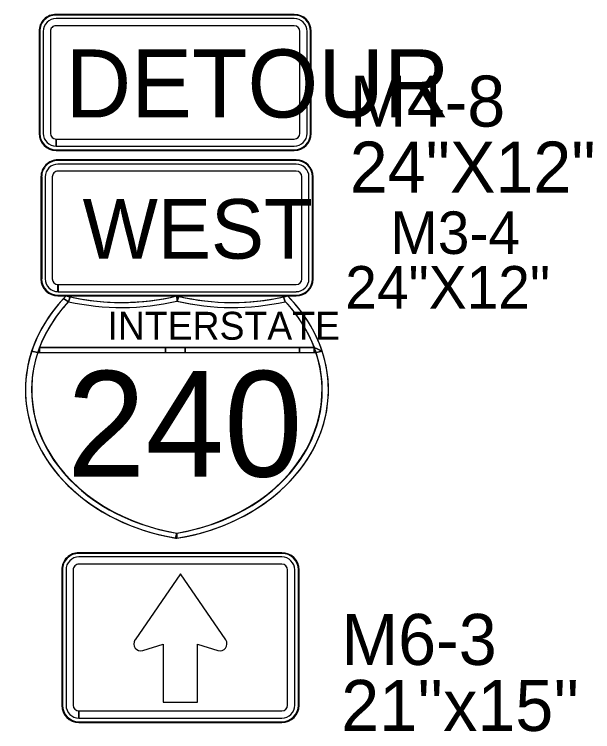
# Model space of a CAD drawing. Extents: x 886234 to 968767, y 455416 to 684046.
# Drawn here: x 909188 to 910208, y 514345 to 515610 of the extents above; entities that cross this region are included whole.
import ezdxf

# ---------------------------------------------------------------- set-up
doc = ezdxf.new("R2010")
doc.units = 0
for name, color, linetype in [('TC DEV SIGN BLACK 239', 7, 'Continuous'), ('TC DEV SIGN BLACK ZERO', 7, 'Continuous'), ('TC DEV SIGN ORANGE', 7, 'Continuous'), ('TC DEV SIGN WHITE', 7, 'Continuous'), ('TC LABEL TEXT', 7, 'Continuous')]:
    doc.layers.add(name, color=color, linetype=linetype)

msp = doc.modelspace()

# ---------------------------------------------------------------- linework, layer by layer
at = {"layer": 'TC DEV SIGN BLACK 239'}
for p, q in [((909684.9, 515346), (909264.8, 515346)), ((909684.9, 515333.5), (909264.8, 515333.5)), ((909242.3, 515323.5), (909242.3, 515143.5)), ((909254.8, 515323.5), (909254.8, 515143.5)), ((909694.9, 515143.5), (909694.9, 515323.5)), ((909707.4, 515143.5), (909707.4, 515323.5)), ((909264.8, 515121), (909264.8, 515133.5)), ((909265, 515133.5), (909684.9, 515133.5)), ((909265, 515133.5), (909265, 515121)), ((909265, 515121), (909684.9, 515121)), ((909659.6, 514653.1), (909301.8, 514653.1)), ((909279, 514630.3), (909279, 514391.7)), ((909291.7, 514630.3), (909291.6, 514391.7)), ((909659.6, 514640.4), (909301.8, 514640.4)), ((909669.7, 514391.7), (909669.7, 514630.3)), ((909682.4, 514391.7), (909682.4, 514630.3)), ((909301.8, 514368.9), (909301.8, 514381.6)), ((909301.9, 514381.6), (909659.6, 514381.6)), ((909301.9, 514381.6), (909301.9, 514368.9)), ((909301.9, 514368.9), (909659.6, 514368.9))]:
    msp.add_line(p, q, dxfattribs=at)
for points in [[(909560.8, 514506.8), (909480.7, 514623.4), (909400.7, 514506.8)], [(909560.8, 514506.8), (909480.7, 514623.4), (909400.7, 514506.8)], [(909560.8, 514506.8), (909480.7, 514623.4), (909400.7, 514506.8)], [(909414.4, 514488.3), (909450.2, 514499.6), (909450.2, 514397.3), (909511.1, 514397.3)], [(909414.4, 514488.3), (909450.2, 514499.6), (909450.2, 514397.3), (909511.1, 514397.3)], [(909414.4, 514488.3), (909450.2, 514499.6), (909450.2, 514397.3), (909511.1, 514397.3)], [(909511.1, 514397.3), (909511.1, 514499.6), (909547, 514488.3)], [(909511.1, 514397.3), (909511.1, 514499.6), (909547, 514488.3)], [(909511.1, 514397.3), (909511.1, 514499.6), (909547, 514488.3)]]:
    msp.add_lwpolyline(points, dxfattribs=at)
for centre, start, end in [((909410.7, 514499.8), 145.5508, 287.601), ((909410.7, 514499.8), 145.5508, 287.601), ((909410.7, 514499.8), 145.5508, 287.601), ((909550.7, 514499.8), 252.399, 34.4492), ((909550.7, 514499.8), 252.399, 34.4492), ((909550.7, 514499.8), 252.399, 34.4492)]:
    msp.add_arc(centre, 12.2, start, end, dxfattribs=at)
for centre, major_axis, start_param, end_param in [((909264.8, 515323.5), (22.5, 0), 1.570796, 3.141593), ((909684.9, 515323.5), (22.5, 0), 0, 1.570796), ((909264.8, 515323.5), (10, 0), 1.570796, 3.141593), ((909684.9, 515323.5), (10, 0), 0, 1.570796), ((909264.8, 515143.5), (22.5, 0), 3.141593, 4.712389), ((909264.8, 515143.5), (10, 0), 3.141593, 4.712389), ((909684.9, 515143.5), (22.5, 0), 4.712389, 6.283185), ((909684.9, 515143.5), (10, 0), 4.712389, 6.283185), ((909301.8, 514630.3), (22.8, 0), 1.570796, 3.141593), ((909659.6, 514630.3), (22.8, 0), 0, 1.570796), ((909301.8, 514630.3), (10.1, 0), 1.570796, 3.141593), ((909659.6, 514630.3), (10.1, 0), 0, 1.570796), ((909301.8, 514391.7), (22.8, 0), 3.141593, 4.712389), ((909301.8, 514391.7), (10.1, 0), 3.141593, 4.712389), ((909659.6, 514391.7), (22.8, 0), 4.712389, 6.283185), ((909659.6, 514391.7), (10.1, 0), 4.712389, 6.283185)]:
    msp.add_ellipse(centre, major_axis=major_axis, ratio=0.999865, start_param=start_param, end_param=end_param, dxfattribs=at)
at = {"layer": 'TC DEV SIGN BLACK ZERO'}
for p, q in [((909681.5, 515610.1), (909261.4, 515610.1)), ((909261.4, 515608.8), (909261.4, 515608.8)), ((909681.5, 515608.8), (909261.4, 515608.8)), ((909681.5, 515608.8), (909681.5, 515608.8)), ((909681.5, 515602.6), (909261.4, 515602.6)), ((909231.4, 515580.1), (909231.4, 515400.1)), ((909232.7, 515580.1), (909232.7, 515400.1)), ((909232.7, 515580.1), (909232.7, 515580.1)), ((909238.9, 515580.1), (909238.9, 515400.1)), ((909251.4, 515580.1), (909251.4, 515400.1)), ((909681.5, 515590.1), (909261.4, 515590.1)), ((909691.5, 515400.1), (909691.5, 515580.1)), ((909704, 515400.1), (909704, 515580.1)), ((909710.2, 515580.1), (909710.2, 515580.1)), ((909710.2, 515400.1), (909710.2, 515580.1)), ((909711.5, 515400.1), (909711.5, 515580.1)), ((909232.7, 515400.1), (909232.7, 515400.1)), ((909261.4, 515377.6), (909261.4, 515390.1)), ((909261.5, 515390.1), (909681.5, 515390.1)), ((909261.5, 515390.1), (909261.5, 515377.6)), ((909710.2, 515400.1), (909710.2, 515400.1)), ((909261.5, 515377.6), (909681.5, 515377.6)), ((909261.4, 515370.1), (909261.4, 515371.3)), ((909261.4, 515371.3), (909261.4, 515371.3)), ((909261.4, 515371.3), (909681.5, 515371.3)), ((909261.4, 515371.3), (909261.4, 515370.1)), ((909261.4, 515370.1), (909681.5, 515370.1)), ((909681.5, 515371.3), (909681.5, 515371.3)), ((909684.9, 515353.5), (909264.8, 515353.5)), ((909264.8, 515352.3), (909264.8, 515352.3)), ((909684.9, 515352.3), (909264.8, 515352.3)), ((909684.9, 515352.3), (909684.9, 515352.3)), ((909234.8, 515323.5), (909234.8, 515143.5)), ((909236.1, 515323.5), (909236.1, 515143.5)), ((909236.1, 515323.5), (909236.1, 515323.5)), ((909713.6, 515323.5), (909713.7, 515323.5)), ((909713.7, 515143.5), (909713.7, 515323.5)), ((909714.9, 515143.5), (909714.9, 515323.5)), ((909236.1, 515143.5), (909236.1, 515143.5)), ((909713.7, 515143.5), (909713.6, 515143.5)), ((909264.8, 515113.5), (909264.8, 515114.8)), ((909264.8, 515114.8), (909264.8, 515114.8)), ((909264.9, 515114.8), (909684.9, 515114.8)), ((909264.9, 515114.8), (909264.9, 515113.5)), ((909264.9, 515113.5), (909684.9, 515113.5)), ((909283.6, 515103.3), (909286.6, 515111.9)), ((909474.9, 515104.3), (909474.6, 515113.6)), ((909474.9, 515105), (909474.6, 515113.6)), ((909662.6, 515111.9), (909665.6, 515103.3)), ((909684.9, 515114.8), (909684.9, 515114.8)), ((909232.3, 515022.4), (909716.9, 515022.4)), ((909454.2, 515022.4), (909232.3, 515022.4)), ((909489.4, 515022.4), (909454.2, 515022.4)), ((909690.7, 515022.4), (909489.4, 515022.4)), ((909716.9, 515022.4), (909690.7, 515022.4)), ((909730.8, 515015.8), (909716.9, 515022.4)), ((909229.1, 515013.5), (909720.1, 515013.5)), ((909229.1, 515013.5), (909232.3, 515013.5)), ((909232.3, 515013.5), (909454.2, 515013.5)), ((909454.2, 515013.5), (909489.4, 515013.5)), ((909489.4, 515013.5), (909690.7, 515013.5)), ((909690.7, 515013.5), (909716.9, 515013.5)), ((909719.8, 515014.2), (909716.9, 515013.5)), ((909716.9, 515013.5), (909720.1, 515013.5)), ((909207.4, 514949.2), (909207.4, 514946.6)), ((909741.8, 514946.5), (909741.8, 514949.3)), ((909474.6, 514686.1), (909474.6, 514695.2)), ((909659.6, 514660.7), (909301.8, 514660.7)), ((909301.8, 514659.4), (909301.8, 514659.5)), ((909659.6, 514659.4), (909301.8, 514659.5)), ((909659.6, 514659.4), (909659.6, 514659.4)), ((909271.4, 514630.3), (909271.4, 514391.7)), ((909272.6, 514630.3), (909272.6, 514391.7)), ((909272.6, 514630.3), (909272.6, 514630.3)), ((909688.7, 514630.3), (909688.7, 514630.3)), ((909688.7, 514391.7), (909688.7, 514630.3)), ((909690, 514391.7), (909690, 514630.3)), ((909272.6, 514391.7), (909272.6, 514391.7)), ((909688.7, 514391.7), (909688.7, 514391.7)), ((909301.8, 514361.3), (909301.8, 514362.6)), ((909301.8, 514362.6), (909301.8, 514362.6)), ((909301.8, 514362.6), (909659.6, 514362.6)), ((909301.8, 514362.6), (909301.8, 514361.3)), ((909301.8, 514361.3), (909659.6, 514361.3)), ((909659.6, 514362.6), (909659.6, 514362.6))]:
    msp.add_line(p, q, dxfattribs=at)
for points in [[(909279.4, 515113.6), (909279.4, 515113.6), (909279.4, 515113.6)], [(909286.6, 515111.9), (909283.6, 515103.3)], [(909474.9, 515113.5), (909474.9, 515105), (909478, 515112.8)], [(909478, 515112.8), (909474.9, 515104.3)], [(909665.6, 515103.3), (909662.6, 515111.9)], [(909669.8, 515113.6), (909669.8, 515113.6), (909669.8, 515113.6)], [(909274.7, 515108.7), (909283.6, 515103.3)], [(909283.6, 515103.3), (909274.7, 515108.7)], [(909474.6, 515104.3), (909474.9, 515105)], [(909232.3, 515022.4), (909232.3, 515013.5)], [(909232.3, 515013.5), (909232.3, 515022.4)], [(909454.2, 515013.5), (909454.2, 515022.4)], [(909454.2, 515022.4), (909454.2, 515013.5)], [(909489.4, 515022.4), (909489.4, 515013.5)], [(909489.4, 515013.5), (909489.4, 515022.4)], [(909690.7, 515013.5), (909690.7, 515022.4)], [(909690.7, 515022.4), (909690.7, 515013.5)], [(909716.9, 515022.4), (909730.8, 515015.8)], [(909716.9, 515013.5), (909716.9, 515022.4)], [(909716.9, 515022.4), (909716.9, 515013.5), (909719.8, 515014.2), (909716.9, 515022.4)], [(909218.4, 515015.8), (909229.1, 515013.5)], [(909229.1, 515013.5), (909218.4, 515015.8)], [(909720.1, 515013.5), (909719.8, 515014.2)], [(909730.8, 515015.8), (909720.1, 515013.5)], [(909720.1, 515013.5), (909730.8, 515015.8)], [(909472.3, 514686.5), (909474.6, 514695.2)], [(909474.6, 514695.2), (909472.3, 514686.5), (909474.6, 514686.1)], [(909474.6, 514695.2), (909474.6, 514686.1)]]:
    msp.add_lwpolyline(points, dxfattribs=at)
for centre, major_axis, ratio, start_param, end_param in [((909261.4, 515580.1), (30, 0), 0.999865, 1.570796, 3.141593), ((909261.4, 515580.1), (28.8, 0), 0.999865, 1.570796, 3.141593), ((909681.5, 515580.1), (30, 0), 0.999865, 0, 1.570796), ((909681.5, 515580.1), (28.8, 0), 0.999865, 0, 1.570796), ((909261.4, 515580.1), (22.5, 0), 0.999865, 1.570796, 3.141593), ((909681.5, 515580.1), (22.5, 0), 0.999865, 0, 1.570796), ((909261.4, 515580.1), (10, 0), 0.999865, 1.570796, 3.141593), ((909681.5, 515580.1), (10, 0), 0.999865, 0, 1.570796), ((909261.4, 515400.1), (30, 0), 0.999865, 3.141593, 4.712389), ((909261.4, 515400.1), (28.8, 0), 0.999865, 3.141593, 4.712389), ((909261.4, 515400.1), (22.5, 0), 0.999865, 3.141593, 4.712389), ((909261.4, 515400.1), (10, 0), 0.999865, 3.141593, 4.712389), ((909681.5, 515400.1), (22.5, 0), 0.999865, 4.712389, 6.283185), ((909681.5, 515400.1), (10, 0), 0.999865, 4.712389, 6.283185), ((909681.5, 515400.1), (30, 0), 0.999865, 4.712389, 6.283185), ((909681.5, 515400.1), (28.8, 0), 0.999865, 4.712389, 6.283185), ((909264.8, 515323.5), (30, 0), 0.999865, 1.570796, 3.141593), ((909264.8, 515323.5), (28.8, 0), 0.999865, 1.570796, 3.141593), ((909684.9, 515323.5), (30, 0), 0.999865, 0, 1.570796), ((909684.9, 515323.5), (28.8, 0), 0.999865, 0, 1.570796), ((909264.8, 515143.5), (30, 0), 0.999865, 3.141593, 4.712389), ((909264.8, 515143.5), (28.8, 0), 0.999865, 3.141593, 4.712389), ((909684.9, 515143.5), (30, 0), 0.999865, 4.712389, 6.283185), ((909684.9, 515143.5), (28.8, 0), 0.999865, 4.712389, 6.283185), ((909541.4, 514947.9), (-334, 0), 0.800002, 5.614188, 7.652625), ((909541.4, 514947.9), (-334, 0), 0.800002, 5.614216, 5.637358), ((909377, 515369.1), (334, 0), 0.800002, 4.415792, 5.008922), ((909377, 515369.1), (334, 0), 0.800002, 4.415856, 4.438209), ((909377, 515369.1), (334, 0), 0.800002, 4.438209, 5.008909), ((909572.2, 515369.1), (334, 0), 0.800002, 4.415856, 5.008986), ((909407.8, 514947.9), (334, 0), 0.800002, 4.913746, 6.952183), ((909572.2, 515369.1), (334, 0), 0.800002, 4.416709, 4.426515), ((909572.2, 515369.1), (334, 0), 0.800002, 4.426515, 4.986569), ((909572.2, 515369.1), (334, 0), 0.800002, 4.986569, 5.008922), ((909407.8, 514947.9), (334, 0), 0.800002, 0.256966, 0.66897), ((909541.4, 514947.9), (-322.9, 0), 0.800002, 5.637358, 7.64558), ((909541.4, 514947.9), (-334, 0), 0.800002, 5.637358, 6.026219), ((909541.4, 514947.9), (-322.9, 0), 0.800002, 5.637358, 6.026219), ((909377, 515369.1), (345.1, 0), 0.800002, 4.438209, 4.999074), ((909377, 515369.1), (345.1, 0), 0.800002, 4.438209, 4.999074), ((909572.2, 515369.1), (345.1, 0), 0.800002, 4.425704, 4.986569), ((909407.8, 514947.9), (322.9, 0), 0.800002, 4.920791, 6.929013), ((909572.3, 515368.7), (344.6, 0), 0.800002, 4.425686, 4.986568), ((909407.8, 514947.9), (322.9, 0), 0.800002, 0.292795, 0.645828), ((909541.4, 514947.9), (-322.9, 0), 0.800002, 5.99039, 6.026219), ((909407.8, 514947.9), (322.9, 0), 0.800002, 0.256966, 0.292795), ((909539.8, 514947.1), (-321.6, 0), 0.800002, 6.022151, 7.649781), ((909541.4, 514947.9), (-334, 0), 0.800002, 6.026219, 6.278259), ((909409.4, 514947.1), (321.6, 0), 0.800002, 4.916934, 6.544356), ((909407.8, 514947.9), (334, 0), 0.800002, 0.005231, 0.256966), ((909541.4, 514947.9), (-334, 0), 0.800002, 0.004927, 1.362388), ((909407.8, 514947.9), (334, 0), 0.800002, 4.913748, 6.277955), ((909407.8, 514947.9), (322.9, 0), 0.800002, 4.920791, 4.921138), ((909541.4, 514947.9), (-334, 0), 0.800002, 1.36935, 1.369438), ((909407.8, 514947.9), (334, 0), 0.800002, 4.913747, 4.913748), ((909301.8, 514630.3), (30.4, 0), 0.999865, 1.570796, 3.141593), ((909301.8, 514630.3), (29.2, 0), 0.999865, 1.570796, 3.141593), ((909659.6, 514630.3), (30.4, 0), 0.999865, 0, 1.570796), ((909659.6, 514630.3), (29.2, 0), 0.999865, 0, 1.570796), ((909301.8, 514391.7), (30.4, 0), 0.999865, 3.141593, 4.712389), ((909301.8, 514391.7), (29.2, 0), 0.999865, 3.141593, 4.712389), ((909659.6, 514391.7), (30.4, 0), 0.999865, 4.712389, 6.283185), ((909659.6, 514391.7), (29.2, 0), 0.999865, 4.712389, 6.283185)]:
    msp.add_ellipse(centre, major_axis=major_axis, ratio=ratio, start_param=start_param, end_param=end_param, dxfattribs=at)
at = {"layer": 'TC DEV SIGN ORANGE'}
for p, q in [((909681.5, 515610.1), (909261.4, 515610.1)), ((909231.4, 515580.1), (909231.4, 515400.1)), ((909711.5, 515400.1), (909711.5, 515580.1)), ((909261.4, 515370.1), (909681.5, 515370.1))]:
    msp.add_line(p, q, dxfattribs=at)
for centre, start_param, end_param in [((909261.4, 515580.1), 1.570796, 3.141593), ((909681.5, 515580.1), 0, 1.570796), ((909261.4, 515400.1), 3.141593, 4.712389), ((909681.5, 515400.1), 4.712389, 6.283185)]:
    msp.add_ellipse(centre, major_axis=(30, 0), ratio=0.999865, start_param=start_param, end_param=end_param, dxfattribs=at)
at = {"layer": 'TC DEV SIGN WHITE'}
for p, q in [((909684.9, 515353.5), (909264.8, 515353.5)), ((909234.8, 515323.5), (909234.8, 515143.5)), ((909714.9, 515143.5), (909714.9, 515323.5)), ((909264.8, 515113.5), (909684.9, 515113.5)), ((909659.6, 514660.7), (909301.8, 514660.7)), ((909271.4, 514630.3), (909271.4, 514391.7)), ((909690, 514391.7), (909690, 514630.3)), ((909301.8, 514361.3), (909659.6, 514361.3))]:
    msp.add_line(p, q, dxfattribs=at)
for centre, major_axis, start_param, end_param in [((909264.8, 515323.5), (30, 0), 1.570796, 3.141593), ((909684.9, 515323.5), (30, 0), 0, 1.570796), ((909264.8, 515143.5), (30, 0), 3.141593, 4.712389), ((909684.9, 515143.5), (30, 0), 4.712389, 6.283185), ((909301.8, 514630.3), (30.4, 0), 1.570796, 3.141593), ((909659.6, 514630.3), (30.4, 0), 0, 1.570796), ((909301.8, 514391.7), (30.4, 0), 3.141593, 4.712389), ((909659.6, 514391.7), (30.4, 0), 4.712389, 6.283185)]:
    msp.add_ellipse(centre, major_axis=major_axis, ratio=0.999865, start_param=start_param, end_param=end_param, dxfattribs=at)

# ---------------------------------------------------------------- texts
at = {"layer": 'TC DEV SIGN BLACK 239'}
msp.add_text('WEST', height=105, rotation=360, dxfattribs=at).set_placement((909308.4, 515179.2))
at = {"layer": 'TC DEV SIGN BLACK ZERO'}
for s, height, p in [('DETOUR', 120, (909278.1, 515428.2)), ('M4-8', 90, (909779.4, 515412.1)), ('24"X12"', 90, (909779.4, 515295.7)), ('INTERSTATE', 49.28, (909352.1, 515036.2)), ('240', 186.16, (909280.8, 514794.9)), ('M6-3', 90, (909764.4, 514462.7)), ("21''x15''", 90, (909764.4, 514346.3))]:
    msp.add_text(s, height=height, rotation=360, dxfattribs=at).set_placement(p)
at = {"layer": 'TC LABEL TEXT'}
for s, p in [('M3-4', (909851.1, 515187.5)), ('24"X12"', (909771.5, 515091.2))]:
    msp.add_text(s, height=75, dxfattribs=at).set_placement(p)

doc.saveas('drawing.dxf')
